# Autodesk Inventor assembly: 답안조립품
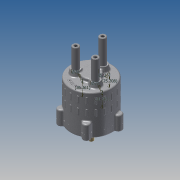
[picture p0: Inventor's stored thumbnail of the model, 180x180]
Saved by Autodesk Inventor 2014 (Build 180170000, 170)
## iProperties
Created: 2016-01
Part Number: 답안조립품
Document SubType Name: Assembly
Designer: Administrator
Mass: 2168.55 g
Surface Area: 1791.57 cm^2
Volume: 441.322 cm^3
Density: 4.91377 g/cm^3
Author: Administrator
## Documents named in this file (14)
- D:\360106V1038\답안조립품.iam
- D:\360106V1038\본체.ipt
- D:\360106V1038\메인 축.ipt
- D:\360106V1038\멈춤링 10 x 1.ipt
- D:\360106V1038\멈춤링 22 x 1.2.ipt
- D:\360106V1038\판캠.ipt
- D:\360106V1038\베어링 NA 4900.ipt
- D:\360106V1038\커버.ipt
- D:\360106V1038\오일실.ipt
- D:\360106V1038\M5x0.8x20.ipt
- D:\360106V1038\슬라이드 축.ipt
- D:\360106V1038\가변 스프링1.ipt
- D:\360106V1038\가변 스프링2.ipt
- D:\360106V1038\가변 스프링3.ipt
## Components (8 placed, 4 different names)
1. M5x0.8x20:1
2. M5x0.8x20:2
3. M5x0.8x20:3
4. M5x0.8x20:4
5. M5x0.8x20:5
6. 가변 스프링1:1
7. 가변 스프링2:1
8. 가변 스프링3:1
